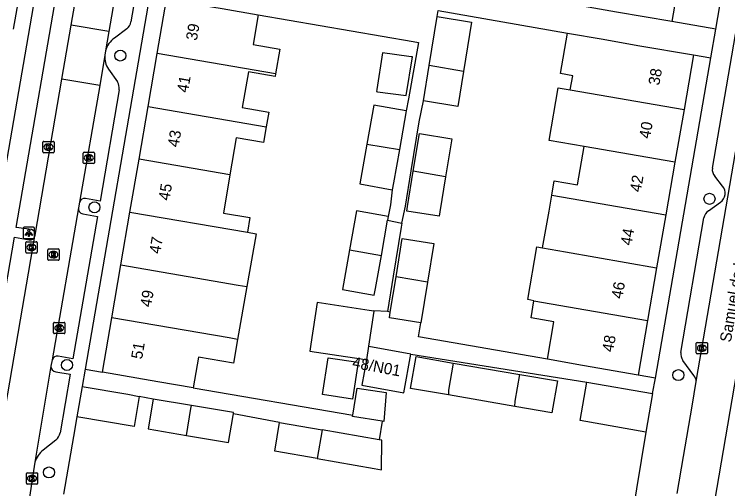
# Model space of a CAD drawing. Extents: x 159822 to 160765, y 380693 to 381634.
# Drawn here: x 160052.1 to 160115.3, y 380895.1 to 380937.1 of the extents above; entities that cross this region are included whole.
import ezdxf

# ---------------------------------------------------------------- set-up
doc = ezdxf.new("R2010")
doc.units = 0
for name, color, linetype in [('IMGEO_Boom', 7, 'Continuous'), ('IMGEO_Erf', 7, 'Continuous'), ('IMGEO_Kolk', 7, 'Continuous'), ('IMGEO_Lichtpunt', 7, 'Continuous'), ('IMGEO_Muur', 7, 'Continuous'), ('IMGEO_Openbare_ruimte_label', 7, 'Continuous'), ('IMGEO_Pand', 7, 'Continuous'), ('IMGEO_Pand_nummerreeks', 7, 'Continuous'), ('IMGEO_Rijbaan_lokaal_open', 7, 'Continuous'), ('IMGEO_Rioolput', 7, 'Continuous'), ('IMGEO_Voetpad_open', 7, 'Continuous')]:
    doc.layers.add(name, color=color, linetype=linetype)

msp = doc.modelspace()

# ---------------------------------------------------------------- linework, layer by layer
at = {"layer": 'IMGEO_Boom'}
for centre in [(160061.473, 380933.474), (160113.694, 380920.784), (160059.182, 380920.033), (160056.742, 380906.059), (160110.938, 380905.167), (160055.147, 380896.541)]:
    msp.add_circle(centre, 0.489, dxfattribs=at)
at = {"layer": 'IMGEO_Erf'}
msp.add_lwpolyline([(160086.435, 380918.634), (160086.359, 380918.263), (160085.652, 380913.924), (160085.142, 380910.789)], dxfattribs=at)
at = {"layer": 'IMGEO_Kolk'}
for p, q in [((160054.606, 380924.944), (160054.606, 380925.796)), ((160054.681, 380925.87), (160055.533, 380925.87)), ((160055.094, 380925.65), (160055.119, 380925.65)), ((160055.607, 380925.796), (160055.607, 380924.944)), ((160055.533, 380924.87), (160054.681, 380924.87)), ((160055.117, 380925.09), (160055.092, 380925.09)), ((160058.182, 380923.983), (160058.182, 380924.835)), ((160058.257, 380924.909), (160059.109, 380924.909)), ((160058.67, 380924.689), (160058.695, 380924.689)), ((160059.183, 380924.835), (160059.183, 380923.983)), ((160058.693, 380924.129), (160058.668, 380924.129)), ((160059.109, 380923.909), (160058.257, 380923.909)), ((160053.092, 380916.056), (160053.092, 380916.908)), ((160053.167, 380916.982), (160054.019, 380916.982)), ((160053.58, 380916.762), (160053.605, 380916.762)), ((160054.093, 380916.908), (160054.093, 380916.056)), ((160054.019, 380915.982), (160053.167, 380915.982)), ((160053.603, 380916.202), (160053.578, 380916.202)), ((160055.561, 380908.915), (160055.561, 380909.767)), ((160055.636, 380909.841), (160056.488, 380909.841)), ((160056.049, 380909.621), (160056.074, 380909.621)), ((160056.562, 380909.767), (160056.562, 380908.915)), ((160056.488, 380908.841), (160055.636, 380908.841)), ((160056.072, 380909.061), (160056.047, 380909.061)), ((160112.519, 380907.132), (160112.519, 380907.984)), ((160112.594, 380908.058), (160113.446, 380908.058)), ((160113.007, 380907.838), (160113.032, 380907.838)), ((160113.52, 380907.984), (160113.52, 380907.132)), ((160113.446, 380907.058), (160112.594, 380907.058)), ((160113.03, 380907.278), (160113.005, 380907.278)), ((160053.145, 380895.589), (160053.145, 380896.441)), ((160053.22, 380896.515), (160054.072, 380896.515)), ((160053.633, 380896.295), (160053.658, 380896.295)), ((160054.146, 380896.441), (160054.146, 380895.589)), ((160053.656, 380895.735), (160053.631, 380895.735)), ((160054.072, 380895.515), (160053.22, 380895.515))]:
    msp.add_line(p, q, dxfattribs=at)
for points in [[(160054.606, 380924.944), (160054.606, 380925.796)], [(160054.681, 380925.87), (160055.533, 380925.87)], [(160054.927, 380925.57), (160055.05, 380925.57), (160055.05, 380925.419), (160055.18, 380925.57), (160055.344, 380925.57), (160055.198, 380925.419), (160055.351, 380925.17), (160055.199, 380925.17), (160055.114, 380925.334), (160055.05, 380925.267), (160055.05, 380925.17), (160054.927, 380925.17), (160054.927, 380925.57)], [(160055.607, 380925.796), (160055.607, 380924.944)], [(160055.533, 380924.87), (160054.681, 380924.87)], [(160058.182, 380923.983), (160058.182, 380924.835)], [(160058.257, 380924.909), (160059.109, 380924.909)], [(160059.183, 380924.835), (160059.183, 380923.983)], [(160058.503, 380924.609), (160058.626, 380924.609), (160058.626, 380924.458), (160058.756, 380924.609), (160058.92, 380924.609), (160058.774, 380924.458), (160058.927, 380924.209), (160058.775, 380924.209), (160058.69, 380924.373), (160058.626, 380924.306), (160058.626, 380924.209), (160058.503, 380924.209), (160058.503, 380924.609)], [(160059.109, 380923.909), (160058.257, 380923.909)], [(160053.092, 380916.056), (160053.092, 380916.908)], [(160053.167, 380916.982), (160054.019, 380916.982)], [(160053.413, 380916.682), (160053.536, 380916.682), (160053.536, 380916.531), (160053.666, 380916.682), (160053.83, 380916.682), (160053.684, 380916.531), (160053.837, 380916.282), (160053.685, 380916.282), (160053.6, 380916.446), (160053.536, 380916.379), (160053.536, 380916.282), (160053.413, 380916.282), (160053.413, 380916.682)], [(160054.093, 380916.908), (160054.093, 380916.056)], [(160054.019, 380915.982), (160053.167, 380915.982)], [(160055.561, 380908.915), (160055.561, 380909.767)], [(160055.636, 380909.841), (160056.488, 380909.841)], [(160055.882, 380909.541), (160056.005, 380909.541), (160056.005, 380909.39), (160056.135, 380909.541), (160056.299, 380909.541), (160056.153, 380909.39), (160056.306, 380909.141), (160056.154, 380909.141), (160056.069, 380909.305), (160056.005, 380909.238), (160056.005, 380909.141), (160055.882, 380909.141), (160055.882, 380909.541)], [(160056.562, 380909.767), (160056.562, 380908.915)], [(160056.488, 380908.841), (160055.636, 380908.841)], [(160112.519, 380907.132), (160112.519, 380907.984)], [(160112.594, 380908.058), (160113.446, 380908.058)], [(160112.84, 380907.758), (160112.963, 380907.758), (160112.963, 380907.607), (160113.093, 380907.758), (160113.257, 380907.758), (160113.111, 380907.607), (160113.264, 380907.358), (160113.112, 380907.358), (160113.027, 380907.522), (160112.963, 380907.455), (160112.963, 380907.358), (160112.84, 380907.358), (160112.84, 380907.758)], [(160113.52, 380907.984), (160113.52, 380907.132)], [(160113.446, 380907.058), (160112.594, 380907.058)], [(160053.145, 380895.589), (160053.145, 380896.441)], [(160053.22, 380896.515), (160054.072, 380896.515)], [(160053.466, 380896.215), (160053.589, 380896.215), (160053.589, 380896.064), (160053.719, 380896.215), (160053.883, 380896.215), (160053.737, 380896.064), (160053.89, 380895.815), (160053.738, 380895.815), (160053.653, 380895.979), (160053.589, 380895.912), (160053.589, 380895.815), (160053.466, 380895.815), (160053.466, 380896.215)], [(160054.146, 380896.441), (160054.146, 380895.589)], [(160054.072, 380895.515), (160053.22, 380895.515)]]:
    msp.add_lwpolyline(points, dxfattribs=at)
for centre, start, end in [((160054.683, 380925.794), 91.55205, 178.44795), ((160054.683, 380925.794), 91.55205, 178.44795), ((160055.531, 380925.794), 1.55205, 88.44795), ((160055.531, 380925.794), 1.55205, 88.44795), ((160054.683, 380924.946), 181.55205, 268.44795), ((160054.683, 380924.946), 181.55205, 268.44795), ((160055.531, 380924.946), 271.55205, 358.44795), ((160055.531, 380924.946), 271.55205, 358.44795), ((160058.259, 380924.833), 91.55205, 178.44795), ((160058.259, 380924.833), 91.55205, 178.44795), ((160059.107, 380924.833), 1.55205, 88.44795), ((160059.107, 380924.833), 1.55205, 88.44795), ((160058.259, 380923.985), 181.55205, 268.44795), ((160058.259, 380923.985), 181.55205, 268.44795), ((160059.107, 380923.985), 271.55205, 358.44795), ((160059.107, 380923.985), 271.55205, 358.44795), ((160053.169, 380916.906), 91.55205, 178.44795), ((160053.169, 380916.906), 91.55205, 178.44795), ((160054.017, 380916.906), 1.55205, 88.44795), ((160054.017, 380916.906), 1.55205, 88.44795), ((160053.169, 380916.058), 181.55205, 268.44795), ((160053.169, 380916.058), 181.55205, 268.44795), ((160054.017, 380916.058), 271.55205, 358.44795), ((160054.017, 380916.058), 271.55205, 358.44795), ((160055.638, 380909.765), 91.55205, 178.44795), ((160055.638, 380909.765), 91.55205, 178.44795), ((160056.486, 380909.765), 1.55205, 88.44795), ((160056.486, 380909.765), 1.55205, 88.44795), ((160055.638, 380908.917), 181.55205, 268.44795), ((160055.638, 380908.917), 181.55205, 268.44795), ((160056.486, 380908.917), 271.55205, 358.44795), ((160056.486, 380908.917), 271.55205, 358.44795), ((160112.596, 380907.982), 91.55205, 178.44795), ((160112.596, 380907.982), 91.55205, 178.44795), ((160113.444, 380907.982), 1.55205, 88.44795), ((160113.444, 380907.982), 1.55205, 88.44795), ((160112.596, 380907.134), 181.55205, 268.44795), ((160112.596, 380907.134), 181.55205, 268.44795), ((160113.444, 380907.134), 271.55205, 358.44795), ((160113.444, 380907.134), 271.55205, 358.44795), ((160053.222, 380896.439), 91.55205, 178.44795), ((160053.222, 380896.439), 91.55205, 178.44795), ((160054.07, 380896.439), 1.55205, 88.44795), ((160054.07, 380896.439), 1.55205, 88.44795), ((160053.222, 380895.591), 181.55205, 268.44795), ((160053.222, 380895.591), 181.55205, 268.44795), ((160054.07, 380895.591), 271.55205, 358.44795), ((160054.07, 380895.591), 271.55205, 358.44795)]:
    msp.add_arc(centre, 0.0765, start, end, dxfattribs=at)
for centre, major_axis, ratio, start_param, end_param in [((160055.093, 380925.37), (-0.387, 0.002), 0.722429, 4.712389, 7.853982), ((160055.118, 380925.37), (-0.39, 0.002), 0.717154, 1.570796, 4.712389), ((160058.669, 380924.409), (-0.387, 0.002), 0.722429, 4.712389, 7.853982), ((160058.694, 380924.409), (-0.39, 0.002), 0.717154, 1.570796, 4.712389), ((160053.579, 380916.482), (-0.387, 0.002), 0.722429, 4.712389, 7.853982), ((160053.604, 380916.482), (-0.39, 0.002), 0.717154, 1.570796, 4.712389), ((160056.048, 380909.341), (-0.387, 0.002), 0.722429, 4.712389, 7.853982), ((160056.073, 380909.341), (-0.39, 0.002), 0.717154, 1.570796, 4.712389), ((160113.006, 380907.558), (-0.387, 0.002), 0.722429, 4.712389, 7.853982), ((160113.031, 380907.558), (-0.39, 0.002), 0.717154, 1.570796, 4.712389), ((160053.632, 380896.015), (-0.387, 0.002), 0.722429, 4.712389, 7.853982), ((160053.657, 380896.015), (-0.39, 0.002), 0.717154, 1.570796, 4.712389)]:
    msp.add_ellipse(centre, major_axis=major_axis, ratio=ratio, start_param=start_param, end_param=end_param, dxfattribs=at)
at = {"layer": 'IMGEO_Lichtpunt'}
for p, q in [((160052.863, 380918.165), (160052.863, 380917.358)), ((160052.863, 380918.165), (160052.863, 380917.358)), ((160053.765, 380918.26), (160052.957, 380918.26)), ((160053.765, 380918.26), (160052.957, 380918.26)), ((160053.859, 380917.358), (160053.859, 380918.165)), ((160053.859, 380917.358), (160053.859, 380918.165)), ((160052.957, 380917.264), (160053.765, 380917.264)), ((160052.957, 380917.264), (160053.765, 380917.264))]:
    msp.add_line(p, q, dxfattribs=at)
for points in [[(160053.237, 380917.829), (160053.276, 380917.801), (160053.088, 380917.539), (160053.05, 380917.566), (160053.237, 380917.829)], [(160053.339, 380917.781), (160053.386, 380917.781), (160053.386, 380917.459), (160053.339, 380917.459), (160053.339, 380917.781)], [(160053.449, 380917.801), (160053.487, 380917.828), (160053.674, 380917.566), (160053.635, 380917.538), (160053.449, 380917.801)]]:
    msp.add_lwpolyline(points, dxfattribs=at)
msp.add_circle((160053.362, 380917.963), 0.0994, dxfattribs=at)
for centre, start, end in [((160052.957, 380918.165), 90, 180), ((160052.957, 380918.165), 90, 180), ((160053.765, 380918.165), 0, 90), ((160053.765, 380918.165), 0, 90), ((160052.957, 380917.358), 180, 270), ((160052.957, 380917.358), 180, 270), ((160053.765, 380917.358), 270, 0), ((160053.765, 380917.358), 270, 360)]:
    msp.add_arc(centre, 0.0946, start, end, dxfattribs=at)
at = {"layer": 'IMGEO_Muur'}
msp.add_lwpolyline([(160057.321, 380899.721), (160056.447, 380894.607)], dxfattribs=at)
at = {"layer": 'IMGEO_Pand'}
for points in [[(160111.368, 380942.289), (160110.369, 380936.484)], [(160052.817, 380940.659), (160051.986, 380935.827)], [(160064.739, 380933.657), (160065.569, 380938.484), (160070.497, 380937.636), (160073.704, 380937.084)], [(160110.369, 380936.484), (160105.442, 380937.333), (160102.937, 380937.764), (160099.68, 380938.325)], [(160073.704, 380937.084), (160073.251, 380934.455), (160075.609, 380934.049), (160075.231, 380931.852)], [(160088.848, 380932.605), (160089.554, 380936.944)], [(160089.554, 380936.944), (160092.607, 380936.447), (160091.895, 380932.076)], [(160101.354, 380930.436), (160101.572, 380931.694), (160100.502, 380931.879), (160101.123, 380935.461)], [(160101.123, 380935.461), (160104.258, 380934.917), (160107.349, 380934.381), (160112.275, 380933.528)], [(160063.933, 380928.976), (160064.739, 380933.657)], [(160075.231, 380931.852), (160064.739, 380933.657)], [(160086.811, 380929.942), (160087.362, 380933.361), (160087.256, 380933.375), (160087.034, 380933.404), (160084.718, 380933.704), (160084.196, 380930.466), (160084.167, 380930.285), (160084.273, 380930.271), (160086.811, 380929.942)], [(160112.275, 380933.528), (160111.436, 380928.688)], [(160088.337, 380929.469), (160088.848, 380932.605)], [(160091.895, 380932.076), (160088.848, 380932.605)], [(160075.231, 380931.852), (160075.193, 380931.633), (160072.832, 380932.04), (160072.285, 380928.862), (160074.623, 380928.46), (160074.401, 380927.173)], [(160091.895, 380932.076), (160091.39, 380928.972), (160088.337, 380929.469)], [(160102.582, 380925.415), (160099.475, 380925.954), (160100.284, 380930.622), (160101.354, 380930.436)], [(160101.354, 380930.436), (160111.436, 380928.688)], [(160086.822, 380928.577), (160083.929, 380929.091), (160083.316, 380925.638)], [(160063.128, 380924.295), (160063.933, 380928.976)], [(160063.933, 380928.976), (160074.401, 380927.173)], [(160086.822, 380928.577), (160086.211, 380925.14)], [(160111.436, 380928.688), (160110.626, 380924.02)], [(160074.401, 380927.173), (160074.16, 380925.77), (160071.755, 380926.184), (160071.191, 380922.907)], [(160087.437, 380923.233), (160087.979, 380926.561), (160090.845, 380926.094), (160090.298, 380922.737)], [(160083.316, 380925.638), (160082.688, 380922.101), (160085.58, 380921.588)], [(160083.316, 380925.638), (160086.211, 380925.14)], [(160099.715, 380921.103), (160099.934, 380922.368), (160101.992, 380922.011), (160102.582, 380925.415)], [(160110.626, 380924.02), (160102.582, 380925.415)], [(160086.211, 380925.14), (160085.687, 380922.19), (160085.58, 380921.588)], [(160062.322, 380919.613), (160063.128, 380924.295)], [(160071.191, 380922.907), (160063.128, 380924.295)], [(160110.626, 380924.02), (160109.817, 380919.352)], [(160071.191, 380922.907), (160070.61, 380919.527), (160072.965, 380919.122), (160072.741, 380917.819)], [(160090.298, 380922.737), (160089.793, 380919.633), (160089.729, 380919.238), (160086.862, 380919.705), (160086.926, 380920.1), (160087.437, 380923.233)], [(160090.298, 380922.737), (160087.437, 380923.233)], [(160098.907, 380916.434), (160099.469, 380919.681), (160099.715, 380921.103)], [(160099.715, 380921.103), (160109.817, 380919.352)], [(160061.517, 380914.932), (160062.322, 380919.613)], [(160062.322, 380919.613), (160072.741, 380917.819)], [(160085.221, 380919.219), (160082.401, 380919.719), (160081.786, 380916.262)], [(160085.221, 380919.219), (160085.163, 380918.893)], [(160109.817, 380919.352), (160109.008, 380914.683)], [(160084.609, 380915.776), (160085.163, 380918.893)], [(160072.741, 380917.819), (160073.506, 380917.687), (160072.688, 380913.009)], [(160085.912, 380913.879), (160086.466, 380917.28), (160089.259, 380916.825), (160088.7, 380913.395)], [(160098.138, 380911.759), (160097.586, 380911.855), (160098.395, 380916.523), (160098.907, 380916.434)], [(160098.907, 380916.434), (160100.925, 380916.084), (160109.008, 380914.683)], [(160081.786, 380916.262), (160081.163, 380912.751), (160083.983, 380912.251), (160084.085, 380912.826), (160084.609, 380915.776)], [(160081.786, 380916.262), (160084.609, 380915.776)], [(160060.711, 380910.251), (160061.517, 380914.932)], [(160061.517, 380914.932), (160071.927, 380913.14), (160072.688, 380913.009)], [(160109.008, 380914.683), (160108.198, 380910.015)], [(160085.402, 380910.747), (160085.912, 380913.879)], [(160088.7, 380913.395), (160085.912, 380913.879)], [(160088.7, 380913.395), (160088.113, 380909.79)], [(160072.688, 380913.009), (160071.87, 380908.329)], [(160083.941, 380910.84), (160083.52, 380910.904), (160078.925, 380911.606), (160078.359, 380907.901), (160078.267, 380907.299), (160082.825, 380906.602), (160083.283, 380906.532)], [(160099.331, 380906.566), (160099.907, 380909.891), (160097.876, 380910.244), (160098.138, 380911.759)], [(160098.138, 380911.759), (160108.198, 380910.015)], [(160083.941, 380910.84), (160083.465, 380907.72)], [(160088.113, 380909.79), (160085.32, 380910.244), (160085.402, 380910.747)], [(160059.881, 380905.424), (160060.711, 380910.251)], [(160071.87, 380908.329), (160071.112, 380908.46), (160060.711, 380910.251)], [(160108.198, 380910.015), (160107.359, 380905.174)], [(160071.87, 380908.329), (160071.501, 380906.216), (160068.405, 380906.749), (160067.938, 380904.038)], [(160083.465, 380907.72), (160083.283, 380906.532)], [(160087.227, 380907.032), (160083.5, 380907.715), (160083.465, 380907.72)], [(160083.283, 380906.532), (160082.869, 380904.272), (160086.596, 380903.589), (160087.227, 380907.032)], [(160082.547, 380906.315), (160082.06, 380903.047), (160079.401, 380903.443), (160079.888, 380906.711), (160082.547, 380906.315)], [(160090.549, 380903.411), (160087.207, 380903.986), (160087.692, 380906.801), (160090.98, 380906.235)], [(160107.359, 380905.174), (160102.433, 380906.028), (160099.331, 380906.566)], [(160090.98, 380906.235), (160090.564, 380903.836), (160090.549, 380903.411)], [(160090.98, 380906.235), (160096.883, 380905.219)], [(160067.938, 380904.038), (160064.809, 380904.576), (160059.881, 380905.424)], [(160096.883, 380905.219), (160100.208, 380904.646), (160099.723, 380901.831), (160096.449, 380902.395)], [(160096.449, 380902.395), (160096.471, 380902.846), (160096.883, 380905.219)], [(160108.066, 380900.123), (160102.238, 380901.133), (160102.827, 380904.534)], [(160102.827, 380904.534), (160108.656, 380903.524)], [(160058.088, 380904.158), (160057.622, 380901.463)], [(160058.088, 380904.158), (160062.124, 380903.464), (160063.157, 380903.27)], [(160082.083, 380901.606), (160082.475, 380904.023), (160085.022, 380903.618), (160084.829, 380901.059), (160084.677, 380901.083)], [(160063.157, 380903.27), (160062.697, 380900.609), (160057.622, 380901.463)], [(160096.449, 380902.395), (160090.549, 380903.411)], [(160108.656, 380903.524), (160108.066, 380900.123)], [(160064.383, 380903.04), (160063.938, 380900.4), (160067.324, 380899.83)], [(160067.779, 380902.468), (160064.383, 380903.04)], [(160067.324, 380899.83), (160067.732, 380902.195), (160067.779, 380902.468)], [(160071.492, 380901.722), (160071.512, 380901.84), (160067.779, 380902.468)], [(160067.324, 380899.83), (160070.537, 380899.289), (160071.068, 380899.2), (160071.468, 380901.581), (160071.492, 380901.722)], [(160084.677, 380901.083), (160082.066, 380901.499), (160082.083, 380901.606)], [(160078.919, 380897.773), (160075.155, 380898.425), (160075.594, 380900.961)], [(160075.594, 380900.961), (160079.355, 380900.309)], [(160079.355, 380900.309), (160078.919, 380897.773)], [(160084.424, 380899.431), (160079.355, 380900.309)], [(160078.919, 380897.773), (160083.985, 380896.896), (160084.608, 380896.788), (160084.665, 380899.389), (160084.424, 380899.431)]]:
    msp.add_lwpolyline(points, dxfattribs=at)
at = {"layer": 'IMGEO_Rijbaan_lokaal_open'}
for points in [[(160068.899, 380984.311), (160060.461, 380935.599)], [(160112.512, 380904.594), (160120.309, 380950.025)], [(160123.634, 380949.453), (160113.751, 380891.769), (160113.376, 380884.116)], [(160057.124, 380936.158), (160058.265, 380942.77)], [(160056.301, 380931.399), (160057.124, 380936.158)], [(160060.461, 380935.599), (160057.124, 380936.158)], [(160060.461, 380935.599), (160060.164, 380933.892)], [(160060.113, 380933.501), (160059.656, 380930.83)], [(160060.164, 380933.892), (160060.113, 380933.501)], [(160053.931, 380917.572), (160056.301, 380931.399)], [(160059.656, 380930.83), (160056.301, 380931.399)], [(160059.656, 380930.83), (160057.846, 380920.497)], [(160057.846, 380920.497), (160057.759, 380919.981)], [(160057.759, 380919.981), (160055.431, 380906.53)], [(160050.041, 380893.234), (160050.388, 380897.134), (160053.902, 380917.466)], [(160053.902, 380917.466), (160053.931, 380917.572)], [(160055.431, 380906.53), (160055.324, 380905.964)], [(160055.324, 380905.964), (160053.889, 380897.443)], [(160110.823, 380894.689), (160111.391, 380897.971), (160112.145, 380902.423), (160112.512, 380904.594)], [(160053.889, 380897.443), (160052.997, 380891.623)]]:
    msp.add_lwpolyline(points, dxfattribs=at)
at = {"layer": 'IMGEO_Rioolput'}
for p, q in [((160055.045, 380915.415), (160055.045, 380916.267)), ((160055.12, 380916.341), (160055.972, 380916.341)), ((160055.533, 380916.121), (160055.558, 380916.121)), ((160056.046, 380916.267), (160056.046, 380915.415)), ((160055.972, 380915.341), (160055.12, 380915.341)), ((160055.556, 380915.561), (160055.531, 380915.561))]:
    msp.add_line(p, q, dxfattribs=at)
for points in [[(160055.045, 380915.415), (160055.045, 380916.267)], [(160055.12, 380916.341), (160055.972, 380916.341)], [(160055.634, 380916.039), (160055.382, 380916.041), (160055.382, 380915.641)], [(160055.382, 380915.641), (160055.506, 380915.641), (160055.506, 380915.803), (160055.517, 380915.803)], [(160055.56, 380915.96), (160055.506, 380915.96), (160055.506, 380915.879)], [(160055.506, 380915.879), (160055.558, 380915.879)], [(160055.564, 380915.774), (160055.635, 380915.641), (160055.775, 380915.641), (160055.71, 380915.767)], [(160056.046, 380916.267), (160056.046, 380915.415)], [(160055.972, 380915.341), (160055.12, 380915.341)]]:
    msp.add_lwpolyline(points, dxfattribs=at)
for centre, radius, start, end in [((160055.122, 380916.265), 0.0765, 91.55205, 178.44795), ((160055.122, 380916.265), 0.0765, 91.55205, 178.44795), ((160055.516, 380915.75), 0.0533, 26.02933, 88.69889), ((160055.542, 380916.068), 0.19, 274.7715, 282.96867), ((160055.566, 380915.864), 0.0964, 77.00612, 93.18647), ((160055.58, 380915.921), 0.0378, 276.66336, 79.67722), ((160055.633, 380915.929), 0.109, 350.36119, 89.41601), ((160055.631, 380915.929), 0.112, 277.58423, 350.98172), ((160055.615, 380915.714), 0.108, 29.51342, 73.79051), ((160055.97, 380916.265), 0.0765, 1.55205, 88.44795), ((160055.97, 380916.265), 0.0765, 1.55205, 88.44795), ((160055.122, 380915.417), 0.0765, 181.55205, 268.44795), ((160055.122, 380915.417), 0.0765, 181.55205, 268.44795), ((160055.97, 380915.417), 0.0765, 271.55205, 358.44795), ((160055.97, 380915.417), 0.0765, 271.55205, 358.44795)]:
    msp.add_arc(centre, radius, start, end, dxfattribs=at)
for centre, major_axis, ratio, start_param, end_param in [((160055.532, 380915.841), (-0.387, 0.002), 0.722429, 4.712389, 7.853982), ((160055.557, 380915.841), (-0.39, 0.002), 0.717154, 1.570796, 4.712389)]:
    msp.add_ellipse(centre, major_axis=major_axis, ratio=ratio, start_param=start_param, end_param=end_param, dxfattribs=at)
at = {"layer": 'IMGEO_Voetpad_open'}
for points in [[(160114.243, 380935.814), (160117.224, 380953.039)], [(160063.748, 380946.756), (160064.183, 380946.715), (160062.416, 380936.469)], [(160053.593, 380918.053), (160052.244, 380918.243), (160056.465, 380942.712), (160057.763, 380942.499)], [(160064.504, 380941.274), (160064.066, 380938.743), (160058.352, 380905.688)], [(160048.492, 380907.352), (160054.211, 380940.418)], [(160113.953, 380923.494), (160116.607, 380938.972)], [(160089.554, 380936.944), (160089.637, 380937.454), (160101.123, 380935.461)], [(160073.704, 380937.084), (160087.43, 380934.721), (160087.9, 380934.641), (160087.009, 380929.629), (160086.822, 380928.577)], [(160114.243, 380935.814), (160110.369, 380936.484)], [(160062.043, 380935.845), (160060.957, 380935.026)], [(160113.802, 380933.264), (160114.243, 380935.814)], [(160112.275, 380933.528), (160113.802, 380933.264)], [(160108.896, 380904.908), (160113.802, 380933.264)], [(160060.421, 380932.271), (160061.209, 380931.144)], [(160061.369, 380930.449), (160059.673, 380920.584), (160058.397, 380920.807)], [(160086.435, 380918.634), (160086.74, 380920.13), (160087.25, 380923.265), (160087.957, 380927.604), (160088.337, 380929.469)], [(160114.86, 380921.914), (160114.159, 380922.782)], [(160085.58, 380921.588), (160085.407, 380920.265), (160085.221, 380919.219)], [(160113.6, 380919.728), (160114.674, 380920.484)], [(160058.144, 380919.445), (160059.444, 380919.225), (160057.256, 380906.6), (160055.957, 380906.839)], [(160111.147, 380907.181), (160113.196, 380919.095)], [(160085.163, 380918.893), (160086.435, 380918.634)], [(160048.475, 380896.479), (160052.085, 380917.399), (160053.4, 380917.161)], [(160085.142, 380910.789), (160083.945, 380910.874), (160083.941, 380910.84)], [(160085.402, 380910.747), (160085.142, 380910.789)], [(160099.331, 380906.566), (160087.911, 380908.544), (160088.113, 380909.79)], [(160087.227, 380907.032), (160102.827, 380904.534)], [(160112.318, 380905.12), (160111.317, 380906.46)], [(160058.352, 380905.688), (160058.088, 380904.158)], [(160058.352, 380905.688), (160059.881, 380905.424)], [(160055.751, 380905.457), (160057.02, 380905.254), (160056.13, 380900.066)], [(160108.896, 380904.908), (160107.359, 380905.174)], [(160108.656, 380903.524), (160108.896, 380904.908)], [(160067.938, 380904.038), (160082.083, 380901.606)], [(160064.383, 380903.04), (160063.157, 380903.27)], [(160057.622, 380901.463), (160057.321, 380899.721), (160056.447, 380894.607)], [(160075.594, 380900.961), (160071.492, 380901.722)], [(160084.677, 380901.083), (160084.424, 380899.431)], [(160108.066, 380900.123), (160106.808, 380892.584)], [(160055.75, 380899.416), (160054.646, 380898.526)]]:
    msp.add_lwpolyline(points, dxfattribs=at)
for centre, radius, start, end in [((160061.427, 380936.637), 1.003, 307.88666, 350.37505), ((160062.075, 380933.4), 1.973, 124.51142, 165.55881), ((160061.885, 380933.291), 1.785, 173.24795, 214.86838), ((160060.391, 380930.59), 0.988, 351.80727, 34.12175), ((160114.828, 380923.361), 0.885, 171.38445, 220.88859), ((160114.075, 380921.289), 1.004, 306.66413, 38.51416), ((160058.302, 380920.331), 0.485, 78.71223, 160.01315), ((160058.239, 380919.919), 0.484, 172.67546, 258.70268), ((160114.175, 380918.915), 0.996, 125.29691, 169.60855), ((160053.481, 380917.615), 0.452, 354.48858, 75.70306), ((160053.47, 380917.611), 0.456, 261.15089, 341.4123), ((160112.306, 380907.074), 1.164, 174.70608, 211.82811), ((160055.86, 380906.402), 0.447, 77.43661, 163.42781), ((160055.835, 380905.961), 0.511, 179.66111, 260.54766), ((160111.791, 380904.627), 0.722, 357.3961, 43.09399), ((160055.144, 380900.206), 0.996, 307.46957, 351.90801), ((160056.02, 380896.76), 2.238, 127.87684, 162.21727)]:
    msp.add_arc(centre, radius, start, end, dxfattribs=at)

# ---------------------------------------------------------------- texts
at = {"layer": 'IMGEO_Openbare_ruimte_label'}
msp.add_text('Samuel de Langestraat', height=1, rotation=80.15138, dxfattribs=at).set_placement((160115.582, 380908.021))
at = {"layer": 'IMGEO_Pand_nummerreeks'}
for s, rotation, p in [('39', 80.23779, (160068.255, 380934.753)), ('38', 80.16387, (160109.242, 380930.785)), ('41', 80.23779, (160067.461, 380930.141)), ('40', 80.16387, (160108.423, 380926.059)), ('43', 80.23779, (160066.63, 380925.307)), ('42', 80.16387, (160107.602, 380921.327)), ('45', 80.23779, (160065.817, 380920.584)), ('44', 80.16253, (160106.782, 380916.605)), ('47', 80.23701, (160065.004, 380915.861)), ('46', 80.16253, (160105.963, 380911.879)), ('49', 80.23701, (160064.192, 380911.139)), ('48', 80.16387, (160105.145, 380907.156)), ('51', 80.23701, (160063.398, 380906.527)), ('48/N01', 349.46904, (160081.976, 380905.832))]:
    msp.add_text(s, height=1, rotation=rotation, dxfattribs=at).set_placement(p)

doc.saveas('drawing.dxf')
